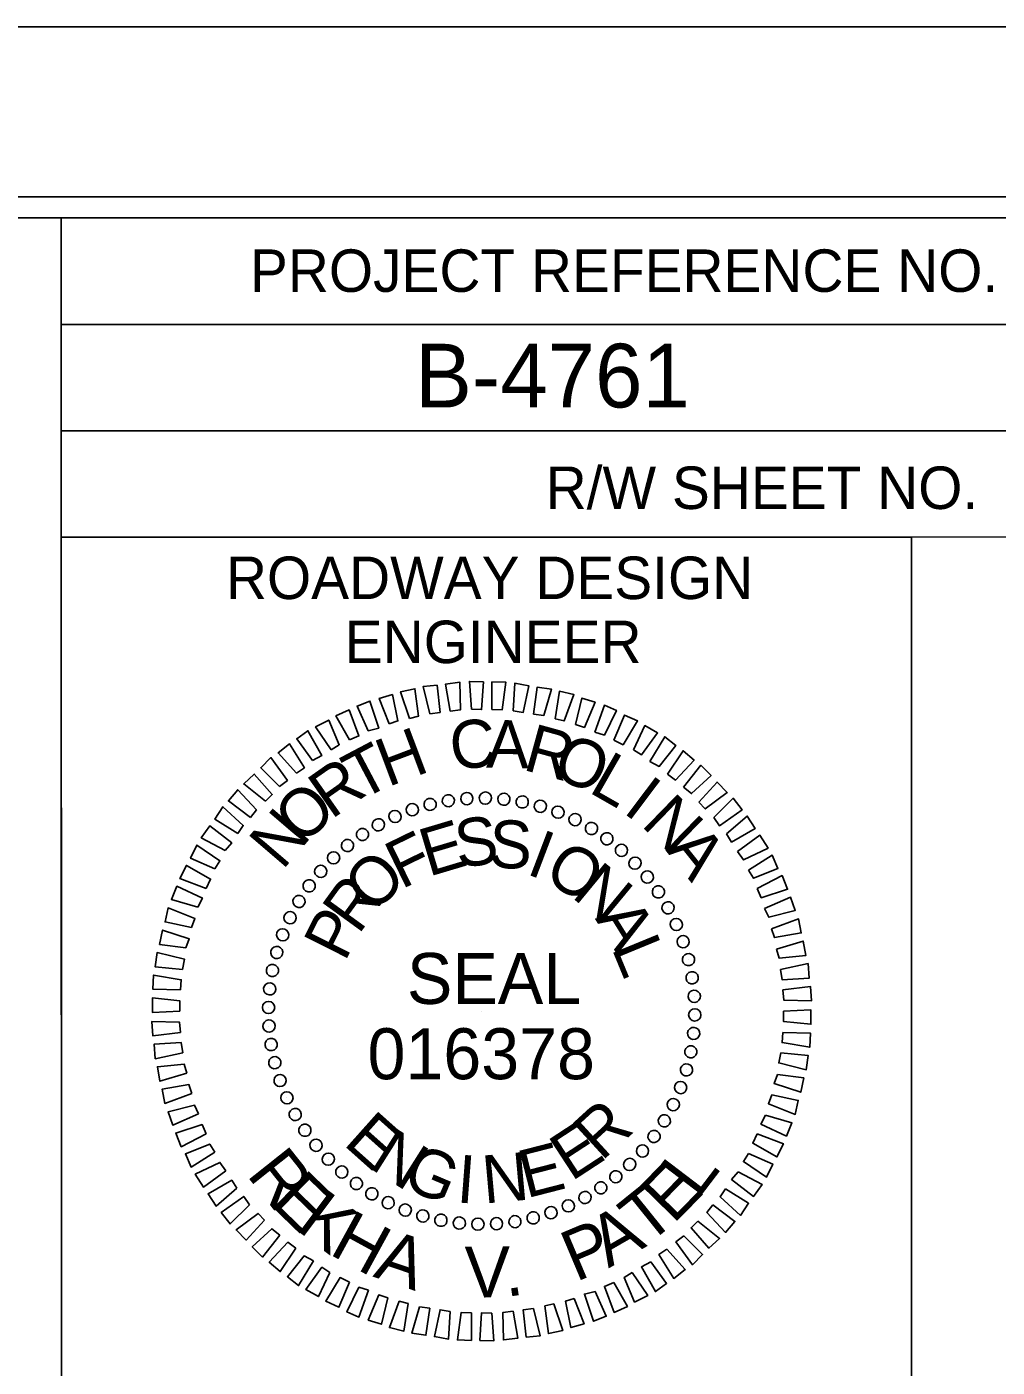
# Model space of a CAD drawing. Extents: x 1593595 to 1594166, y 741647 to 741854.
# Drawn here: x 1594114.83 to 1594128.53, y 741815.33 to 741834.26 of the extents above; entities that cross this region are included whole.
import ezdxf

# ---------------------------------------------------------------- set-up
doc = ezdxf.new("R2010")
doc.units = 0
for name, color, linetype in [('Sheet Cutting Line CELL', 7, 'Continuous'), ('Sheet Data Field CELL', 7, 'Continuous'), ('Sheet Plan CELL', 7, 'Continuous'), ('Sheet Plan Layout CELL', 7, 'Continuous'), ('Sheet Plot Border Inside CELL', 7, 'Continuous'), ('Sheet Plot Border Outside CELL', 7, 'Continuous'), ('Sheet Professional Seal CELL', 7, 'Continuous')]:
    doc.layers.add(name, color=color, linetype=linetype)

msp = doc.modelspace()

# ---------------------------------------------------------------- linework, layer by layer
at = {"layer": 'Sheet Cutting Line CELL'}
msp.add_line((1594141.358, 741834.259), (1593939.338, 741834.259), dxfattribs=at)
at = {"layer": 'Sheet Plan CELL'}
for p, q in [((1594115.31, 741830.056), (1594139.316, 741830.054)), ((1594115.312, 741828.551), (1594139.316, 741828.554)), ((1594115.312, 741828.551), (1594139.316, 741828.554)), ((1594115.312, 741828.551), (1594115.312, 741827.053)), ((1594127.318, 741827.053), (1594127.319, 741813.557))]:
    msp.add_line(p, q, dxfattribs=at)
for points in [[(1593959.316, 741705.56), (1593959.313, 741831.557), (1594115.312, 741831.562), (1594115.313, 741813.554), (1594139.318, 741813.553), (1594139.318, 741705.56)], [(1594139.321, 741831.56), (1593959.316, 741831.56), (1593959.316, 741705.56), (1594139.318, 741705.56)], [(1594115.312, 741831.562), (1594139.321, 741831.56), (1594139.316, 741828.554), (1594115.312, 741828.551)], [(1594115.312, 741827.053), (1594127.318, 741827.053), (1594127.318, 741813.551), (1594115.313, 741813.554)], [(1594127.318, 741827.053), (1594139.316, 741827.054), (1594139.318, 741813.553), (1594127.318, 741813.551)]]:
    msp.add_lwpolyline(points, close=True, dxfattribs=at)
at = {"layer": 'Sheet Plan Layout CELL'}
msp.add_lwpolyline([(1594110.606, 741806.182), (1594139.319, 741806.182), (1594139.322, 741831.56), (1594110.606, 741831.56)], close=True, dxfattribs=at)
at = {"layer": 'Sheet Plot Border Inside CELL'}
msp.add_lwpolyline([(1593940.898, 741705.259), (1594140.816, 741705.26), (1594140.818, 741831.859), (1593940.898, 741831.859)], close=True, dxfattribs=at)
at = {"layer": 'Sheet Plot Border Outside CELL'}
msp.add_lwpolyline([(1593939.338, 741702.859), (1594141.358, 741702.859), (1594141.358, 741834.259), (1593939.338, 741834.259)], close=True, dxfattribs=at)
at = {"layer": 'Sheet Professional Seal CELL'}
for p, q in [((1594120.516, 741823.279), (1594120.516, 741823.279)), ((1594120.78, 741823.327), (1594120.78, 741823.327)), ((1594121.038, 741823.363), (1594121.038, 741823.363)), ((1594121.302, 741823.369), (1594121.302, 741823.369)), ((1594121.566, 741823.351), (1594121.566, 741823.351)), ((1594121.824, 741823.309), (1594121.824, 741823.309)), ((1594122.076, 741823.255), (1594122.076, 741823.255)), ((1594120.024, 741823.111), (1594120.024, 741823.111)), ((1594120.264, 741823.207), (1594120.264, 741823.207)), ((1594122.328, 741823.171), (1594122.328, 741823.171)), ((1594122.568, 741823.063), (1594122.568, 741823.063)), ((1594119.562, 741822.853), (1594119.562, 741822.853)), ((1594119.79, 741822.991), (1594119.79, 741822.991)), ((1594122.802, 741822.943), (1594122.802, 741822.943)), ((1594119.352, 741822.703), (1594119.352, 741822.703)), ((1594123.018, 741822.793), (1594123.018, 741822.793)), ((1594119.154, 741822.523), (1594119.154, 741822.523)), ((1594123.228, 741822.631), (1594123.228, 741822.631)), ((1594118.974, 741822.337), (1594118.974, 741822.337)), ((1594123.414, 741822.451), (1594123.414, 741822.451)), ((1594118.812, 741822.127), (1594118.812, 741822.127)), ((1594123.594, 741822.253), (1594123.594, 741822.253)), ((1594118.662, 741821.911), (1594118.662, 741821.911)), ((1594123.744, 741822.043), (1594123.744, 741822.043)), ((1594123.882, 741821.815), (1594123.882, 741821.815)), ((1594118.542, 741821.677), (1594118.542, 741821.677)), ((1594124.002, 741821.581), (1594124.002, 741821.581)), ((1594118.434, 741821.437), (1594118.434, 741821.437)), ((1594124.098, 741821.341), (1594124.098, 741821.341)), ((1594118.35, 741821.185), (1594118.35, 741821.185)), ((1594124.17, 741821.089), (1594124.17, 741821.089)), ((1594118.296, 741820.933), (1594118.296, 741820.933)), ((1594124.218, 741820.825), (1594124.218, 741820.825)), ((1594118.254, 741820.675), (1594118.254, 741820.675)), ((1594118.236, 741820.411), (1594118.236, 741820.411)), ((1594124.254, 741820.567), (1594124.254, 741820.567)), ((1594121.248, 741820.357), (1594121.248, 741820.357)), ((1594124.26, 741820.303), (1594124.26, 741820.303)), ((1594118.242, 741820.147), (1594118.242, 741820.147)), ((1594124.242, 741820.039), (1594124.242, 741820.039)), ((1594118.278, 741819.889), (1594118.278, 741819.889)), ((1594124.2, 741819.781), (1594124.2, 741819.781)), ((1594118.326, 741819.625), (1594118.326, 741819.625)), ((1594124.146, 741819.529), (1594124.146, 741819.529)), ((1594118.398, 741819.373), (1594118.398, 741819.373)), ((1594124.062, 741819.277), (1594124.062, 741819.277)), ((1594118.494, 741819.133), (1594118.494, 741819.133)), ((1594118.614, 741818.899), (1594118.614, 741818.899)), ((1594123.954, 741819.037), (1594123.954, 741819.037)), ((1594123.834, 741818.803), (1594123.834, 741818.803)), ((1594118.752, 741818.671), (1594118.752, 741818.671)), ((1594123.684, 741818.587), (1594123.684, 741818.587)), ((1594118.902, 741818.461), (1594118.902, 741818.461)), ((1594123.522, 741818.377), (1594123.522, 741818.377)), ((1594119.082, 741818.263), (1594119.082, 741818.263)), ((1594123.342, 741818.191), (1594123.342, 741818.191)), ((1594119.268, 741818.083), (1594119.268, 741818.083)), ((1594123.144, 741818.011), (1594123.144, 741818.011)), ((1594119.478, 741817.921), (1594119.478, 741817.921)), ((1594119.694, 741817.771), (1594119.694, 741817.771)), ((1594122.934, 741817.861), (1594122.934, 741817.861)), ((1594119.928, 741817.651), (1594119.928, 741817.651)), ((1594122.472, 741817.603), (1594122.472, 741817.603)), ((1594122.706, 741817.723), (1594122.706, 741817.723)), ((1594120.168, 741817.543), (1594120.168, 741817.543)), ((1594120.42, 741817.459), (1594120.42, 741817.459)), ((1594120.672, 741817.405), (1594120.672, 741817.405)), ((1594120.93, 741817.363), (1594120.93, 741817.363)), ((1594121.716, 741817.387), (1594121.716, 741817.387)), ((1594121.98, 741817.435), (1594121.98, 741817.435)), ((1594122.232, 741817.507), (1594122.232, 741817.507)), ((1594121.194, 741817.345), (1594121.194, 741817.345)), ((1594121.458, 741817.351), (1594121.458, 741817.351))]:
    msp.add_line(p, q, dxfattribs=at)
for points in [[(1594120.516, 741824.557), (1594120.42, 741824.941), (1594120.618, 741824.959), (1594120.66, 741824.575)], [(1594120.804, 741824.593), (1594120.738, 741824.977), (1594120.942, 741825.001), (1594120.948, 741824.611)], [(1594121.104, 741824.623), (1594121.074, 741825.013), (1594121.272, 741825.007), (1594121.248, 741824.617)], [(1594121.392, 741824.617), (1594121.392, 741825.007), (1594121.59, 741825.001), (1594121.536, 741824.611)], [(1594121.692, 741824.599), (1594121.716, 741824.989), (1594121.914, 741824.953), (1594121.836, 741824.575)], [(1594121.98, 741824.551), (1594122.034, 741824.935), (1594122.232, 741824.905), (1594122.124, 741824.533)], [(1594119.94, 741824.413), (1594119.802, 741824.773), (1594119.988, 741824.827), (1594120.066, 741824.455)], [(1594120.228, 741824.491), (1594120.102, 741824.869), (1594120.306, 741824.911), (1594120.354, 741824.521)], [(1594122.286, 741824.485), (1594122.346, 741824.875), (1594122.55, 741824.827), (1594122.412, 741824.455)], [(1594122.574, 741824.407), (1594122.664, 741824.779), (1594122.85, 741824.719), (1594122.7, 741824.365)], [(1594119.382, 741824.191), (1594119.19, 741824.527), (1594119.376, 741824.611), (1594119.514, 741824.245)], [(1594119.646, 741824.317), (1594119.49, 741824.665), (1594119.67, 741824.737), (1594119.796, 741824.353)], [(1594122.844, 741824.299), (1594122.982, 741824.677), (1594123.15, 741824.605), (1594122.982, 741824.257)], [(1594119.124, 741824.047), (1594118.902, 741824.371), (1594119.088, 741824.467), (1594119.238, 741824.119)], [(1594123.114, 741824.185), (1594123.264, 741824.539), (1594123.45, 741824.455), (1594123.246, 741824.119)], [(1594123.39, 741824.047), (1594123.552, 741824.389), (1594123.732, 741824.287), (1594123.504, 741823.975)], [(1594118.86, 741823.897), (1594118.638, 741824.203), (1594118.794, 741824.317), (1594118.992, 741823.969)], [(1594123.624, 741823.885), (1594123.834, 741824.233), (1594123.99, 741824.107), (1594123.756, 741823.813)], [(1594118.632, 741823.717), (1594118.374, 741824.005), (1594118.536, 741824.131), (1594118.746, 741823.795)], [(1594123.87, 741823.705), (1594124.092, 741824.035), (1594124.248, 741823.903), (1594123.984, 741823.621)], [(1594118.392, 741823.531), (1594118.128, 741823.795), (1594118.272, 741823.939), (1594118.506, 741823.615)], [(1594124.098, 741823.519), (1594124.344, 741823.831), (1594124.488, 741823.687), (1594124.212, 741823.429)], [(1594118.194, 741823.321), (1594117.888, 741823.567), (1594118.038, 741823.705), (1594118.29, 741823.417)], [(1594117.984, 741823.093), (1594117.672, 741823.327), (1594117.804, 741823.483), (1594118.068, 741823.201)], [(1594124.314, 741823.309), (1594124.572, 741823.591), (1594124.716, 741823.447), (1594124.404, 741823.213)], [(1594117.804, 741822.865), (1594117.48, 741823.069), (1594117.594, 741823.243), (1594117.882, 741822.979)], [(1594124.524, 741823.093), (1594124.8, 741823.363), (1594124.926, 741823.201), (1594124.608, 741822.973)], [(1594124.704, 741822.859), (1594124.998, 741823.111), (1594125.112, 741822.937), (1594124.776, 741822.745)], [(1594117.624, 741822.625), (1594117.288, 741822.805), (1594117.408, 741822.973), (1594117.72, 741822.733)], [(1594117.48, 741822.367), (1594117.138, 741822.517), (1594117.228, 741822.703), (1594117.552, 741822.481)], [(1594124.86, 741822.613), (1594125.178, 741822.841), (1594125.292, 741822.661), (1594124.944, 741822.493)], [(1594125.016, 741822.349), (1594125.352, 741822.559), (1594125.43, 741822.373), (1594125.088, 741822.235)], [(1594117.36, 741822.091), (1594116.988, 741822.229), (1594117.078, 741822.415), (1594117.42, 741822.223)], [(1594117.24, 741821.827), (1594116.868, 741821.935), (1594116.946, 741822.121), (1594117.306, 741821.953)], [(1594125.136, 741822.091), (1594125.49, 741822.271), (1594125.568, 741822.079), (1594125.196, 741821.959)], [(1594125.244, 741821.809), (1594125.61, 741821.965), (1594125.676, 741821.779), (1594125.304, 741821.683)], [(1594117.15, 741821.539), (1594116.778, 741821.617), (1594116.82, 741821.815), (1594117.198, 741821.665)], [(1594125.34, 741821.521), (1594125.724, 741821.659), (1594125.76, 741821.461), (1594125.382, 741821.395)], [(1594117.072, 741821.251), (1594116.7, 741821.299), (1594116.742, 741821.503), (1594117.12, 741821.377)], [(1594125.412, 741821.233), (1594125.79, 741821.347), (1594125.826, 741821.143), (1594125.448, 741821.107)], [(1594117.024, 741820.945), (1594116.64, 741820.981), (1594116.664, 741821.185), (1594117.054, 741821.089)], [(1594125.466, 741820.945), (1594125.856, 741821.029), (1594125.874, 741820.825), (1594125.49, 741820.801)], [(1594116.994, 741820.657), (1594116.604, 741820.669), (1594116.616, 741820.867), (1594117.006, 741820.801)], [(1594125.502, 741820.657), (1594125.892, 741820.705), (1594125.904, 741820.501), (1594125.514, 741820.513)], [(1594116.988, 741820.357), (1594116.598, 741820.339), (1594116.598, 741820.543), (1594116.988, 741820.501)], [(1594116.994, 741820.057), (1594116.604, 741820.009), (1594116.592, 741820.213), (1594116.982, 741820.201)], [(1594125.508, 741820.357), (1594125.898, 741820.375), (1594125.898, 741820.171), (1594125.508, 741820.213)], [(1594125.502, 741820.057), (1594125.892, 741820.045), (1594125.88, 741819.847), (1594125.49, 741819.913)], [(1594117.03, 741819.769), (1594116.64, 741819.685), (1594116.622, 741819.889), (1594117.006, 741819.913)], [(1594125.472, 741819.769), (1594125.856, 741819.733), (1594125.832, 741819.529), (1594125.442, 741819.625)], [(1594117.084, 741819.481), (1594116.706, 741819.367), (1594116.67, 741819.571), (1594117.048, 741819.607)], [(1594125.424, 741819.463), (1594125.796, 741819.415), (1594125.754, 741819.211), (1594125.376, 741819.337)], [(1594117.156, 741819.193), (1594116.772, 741819.055), (1594116.736, 741819.253), (1594117.114, 741819.319)], [(1594125.346, 741819.175), (1594125.718, 741819.097), (1594125.676, 741818.899), (1594125.298, 741819.049)], [(1594117.252, 741818.905), (1594116.886, 741818.749), (1594116.82, 741818.935), (1594117.192, 741819.031)], [(1594125.256, 741818.887), (1594125.628, 741818.779), (1594125.55, 741818.593), (1594125.19, 741818.761)], [(1594117.36, 741818.623), (1594117.006, 741818.443), (1594116.928, 741818.635), (1594117.3, 741818.755)], [(1594125.136, 741818.623), (1594125.508, 741818.485), (1594125.418, 741818.299), (1594125.076, 741818.491)], [(1594117.48, 741818.365), (1594117.144, 741818.155), (1594117.066, 741818.341), (1594117.408, 741818.479)], [(1594125.016, 741818.347), (1594125.358, 741818.197), (1594125.268, 741818.011), (1594124.944, 741818.233)], [(1594117.636, 741818.101), (1594117.318, 741817.873), (1594117.204, 741818.053), (1594117.552, 741818.221)], [(1594117.792, 741817.855), (1594117.498, 741817.603), (1594117.384, 741817.777), (1594117.72, 741817.969)], [(1594124.872, 741818.089), (1594125.208, 741817.909), (1594125.088, 741817.741), (1594124.776, 741817.981)], [(1594117.972, 741817.621), (1594117.696, 741817.351), (1594117.57, 741817.513), (1594117.888, 741817.741)], [(1594124.692, 741817.849), (1594125.016, 741817.645), (1594124.902, 741817.471), (1594124.614, 741817.735)], [(1594124.512, 741817.621), (1594124.824, 741817.387), (1594124.692, 741817.231), (1594124.428, 741817.513)], [(1594118.182, 741817.405), (1594117.924, 741817.123), (1594117.78, 741817.267), (1594118.092, 741817.501)], [(1594124.302, 741817.393), (1594124.608, 741817.147), (1594124.458, 741817.009), (1594124.206, 741817.297)], [(1594118.398, 741817.195), (1594118.152, 741816.883), (1594118.008, 741817.027), (1594118.284, 741817.285)], [(1594124.104, 741817.183), (1594124.368, 741816.919), (1594124.224, 741816.775), (1594123.99, 741817.099)], [(1594118.626, 741817.009), (1594118.404, 741816.679), (1594118.248, 741816.811), (1594118.512, 741817.093)], [(1594123.864, 741816.997), (1594124.122, 741816.709), (1594123.96, 741816.583), (1594123.75, 741816.919)], [(1594118.872, 741816.829), (1594118.662, 741816.481), (1594118.506, 741816.607), (1594118.74, 741816.901)], [(1594123.636, 741816.817), (1594123.858, 741816.511), (1594123.702, 741816.397), (1594123.504, 741816.745)], [(1594119.106, 741816.667), (1594118.944, 741816.325), (1594118.764, 741816.427), (1594118.992, 741816.739)], [(1594123.372, 741816.667), (1594123.594, 741816.343), (1594123.408, 741816.247), (1594123.258, 741816.595)], [(1594119.382, 741816.529), (1594119.232, 741816.175), (1594119.046, 741816.259), (1594119.25, 741816.595)], [(1594119.652, 741816.415), (1594119.514, 741816.037), (1594119.346, 741816.109), (1594119.514, 741816.457)], [(1594123.114, 741816.523), (1594123.306, 741816.187), (1594123.12, 741816.103), (1594122.982, 741816.469)], [(1594119.922, 741816.307), (1594119.832, 741815.935), (1594119.646, 741815.995), (1594119.796, 741816.349)], [(1594120.21, 741816.229), (1594120.15, 741815.839), (1594119.946, 741815.887), (1594120.084, 741816.259)], [(1594122.268, 741816.223), (1594122.394, 741815.845), (1594122.19, 741815.803), (1594122.142, 741816.193)], [(1594122.556, 741816.301), (1594122.694, 741815.941), (1594122.508, 741815.887), (1594122.43, 741816.259)], [(1594122.85, 741816.397), (1594123.006, 741816.049), (1594122.826, 741815.977), (1594122.7, 741816.361)], [(1594120.516, 741816.163), (1594120.462, 741815.779), (1594120.264, 741815.809), (1594120.372, 741816.181)], [(1594120.804, 741816.115), (1594120.78, 741815.725), (1594120.582, 741815.761), (1594120.66, 741816.139)], [(1594121.104, 741816.097), (1594121.104, 741815.707), (1594120.906, 741815.713), (1594120.96, 741816.103)], [(1594121.392, 741816.091), (1594121.422, 741815.701), (1594121.224, 741815.707), (1594121.248, 741816.097)], [(1594121.692, 741816.121), (1594121.758, 741815.737), (1594121.554, 741815.713), (1594121.548, 741816.103)], [(1594121.98, 741816.157), (1594122.076, 741815.773), (1594121.878, 741815.755), (1594121.836, 741816.139)]]:
    msp.add_lwpolyline(points, close=True, dxfattribs=at)
for centre, major_axis in [((1594120.777, 741823.329), (-0.0135, 0.0853)), ((1594121.038, 741823.359), (-0.006, 0.0862)), ((1594121.3, 741823.366), (0.0015, 0.0864)), ((1594121.562, 741823.35), (0.009, 0.0859)), ((1594120.268, 741823.202), (-0.0281, 0.0817)), ((1594120.52, 741823.277), (-0.0209, 0.0838)), ((1594121.822, 741823.311), (0.0165, 0.0848)), ((1594122.077, 741823.25), (0.0238, 0.0831)), ((1594122.326, 741823.167), (0.031, 0.0807)), ((1594119.789, 741822.989), (-0.0419, 0.0756)), ((1594120.024, 741823.106), (-0.0351, 0.0789)), ((1594122.567, 741823.062), (0.0379, 0.0777)), ((1594119.565, 741822.852), (-0.0483, 0.0716)), ((1594122.798, 741822.937), (0.0445, 0.0741)), ((1594123.017, 741822.792), (0.0508, 0.0699)), ((1594119.354, 741822.696), (-0.0544, 0.0671)), ((1594123.222, 741822.628), (0.0567, 0.0652)), ((1594119.157, 741822.522), (-0.06, 0.0622)), ((1594123.413, 741822.447), (0.0622, 0.06)), ((1594118.976, 741822.331), (-0.0652, 0.0567)), ((1594123.587, 741822.251), (0.0671, 0.0544)), ((1594118.813, 741822.126), (-0.0699, 0.0508)), ((1594123.743, 741822.04), (0.0716, 0.0483)), ((1594118.668, 741821.907), (-0.0741, 0.0445)), ((1594123.88, 741821.816), (0.0756, 0.0419)), ((1594118.543, 741821.676), (-0.0777, 0.0379)), ((1594118.438, 741821.435), (-0.0807, 0.031)), ((1594123.997, 741821.581), (0.0789, 0.0351)), ((1594124.093, 741821.337), (0.0817, 0.0281)), ((1594118.355, 741821.186), (-0.0831, 0.0238)), ((1594124.168, 741821.085), (0.0838, 0.0209)), ((1594118.293, 741820.931), (-0.0848, 0.0165)), ((1594124.22, 741820.828), (0.0853, 0.0135)), ((1594118.255, 741820.671), (-0.0859, 0.009)), ((1594124.25, 741820.567), (0.0862, 0.006)), ((1594118.239, 741820.409), (-0.0864, 0.0015)), ((1594124.257, 741820.304), (0.0864, -0.0015)), ((1594118.245, 741820.147), (-0.0862, -0.006)), ((1594124.241, 741820.042), (0.0859, -0.009)), ((1594118.275, 741819.886), (-0.0853, -0.0135)), ((1594124.202, 741819.783), (0.0848, -0.0165)), ((1594118.327, 741819.629), (-0.0838, -0.0209)), ((1594118.402, 741819.377), (-0.0817, -0.0281)), ((1594124.141, 741819.527), (0.0831, -0.0238)), ((1594124.057, 741819.278), (0.0807, -0.031)), ((1594118.498, 741819.133), (-0.0789, -0.0351)), ((1594123.953, 741819.037), (0.0777, -0.0379)), ((1594118.615, 741818.898), (-0.0756, -0.0419)), ((1594123.827, 741818.807), (0.0741, -0.0445)), ((1594118.753, 741818.674), (-0.0716, -0.0483)), ((1594123.682, 741818.588), (0.0699, -0.0508)), ((1594118.909, 741818.463), (-0.0671, -0.0544)), ((1594119.083, 741818.266), (-0.0622, -0.06)), ((1594123.519, 741818.382), (0.0652, -0.0567)), ((1594119.273, 741818.085), (-0.0567, -0.0652)), ((1594123.142, 741818.018), (0.0544, -0.0671)), ((1594123.338, 741818.192), (0.06, -0.0622)), ((1594119.479, 741817.922), (-0.0508, -0.0699)), ((1594122.931, 741817.862), (0.0483, -0.0716)), ((1594119.698, 741817.777), (-0.0445, -0.0741)), ((1594119.928, 741817.652), (-0.0379, -0.0777)), ((1594122.707, 741817.725), (0.0419, -0.0756)), ((1594120.169, 741817.547), (-0.031, -0.0807)), ((1594120.418, 741817.464), (-0.0238, -0.0831)), ((1594122.227, 741817.511), (0.0281, -0.0817)), ((1594122.472, 741817.607), (0.0351, -0.0789)), ((1594120.673, 741817.403), (-0.0165, -0.0848)), ((1594120.933, 741817.364), (-0.009, -0.0859)), ((1594121.195, 741817.348), (-0.0015, -0.0864)), ((1594121.458, 741817.355), (0.006, -0.0862)), ((1594121.718, 741817.384), (0.0135, -0.0853)), ((1594121.976, 741817.437), (0.0209, -0.0838))]:
    msp.add_ellipse(centre, major_axis=major_axis, ratio=0.999708, dxfattribs=at)

# ---------------------------------------------------------------- texts
at = {"layer": 'Sheet Data Field CELL'}
msp.add_text(' B-4761  ', height=0.9, rotation=0, dxfattribs=at).set_placement((1594119.973, 741828.883))
at = {"layer": 'Sheet Plan CELL'}
for s, height, p in [('PROJECT REFERENCE NO.', 0.60001, (1594117.976, 741830.515)), ('R/W SHEET NO.', 0.60001, (1594122.152, 741827.449)), ('ROADWAY DESIGN', 0.60001, (1594117.637, 741826.177)), ('ENGINEER', 0.6, (1594119.315, 741825.272))]:
    msp.add_text(s, height=height, rotation=0, dxfattribs=at).set_placement(p)
at = {"layer": 'Sheet Professional Seal CELL'}
for s, height, rotation, p in [('C', 0.677, 6.2199, (1594120.834, 741823.759)), ('A', 0.677, 359.0203, (1594121.308, 741823.795)), ('R', 0.677, 344.6211, (1594121.812, 741823.771)), ('H', 0.677, 20.6195, (1594119.922, 741823.519)), ('O', 0.677, 337.4212, (1594122.214, 741823.681)), ('T', 0.677, 27.8198, (1594119.532, 741823.321)), ('L', 0.677, 330.2209, (1594122.742, 741823.459)), ('R', 0.677, 35.0205, (1594119.124, 741823.057)), ('I', 0.677, 323.0201, (1594123.228, 741823.171)), ('O', 0.677, 42.2217, (1594118.71, 741822.685)), ('N', 0.677, 315.8189, (1594123.486, 741822.985)), ('N', 0.677, 49.4235, (1594118.434, 741822.337)), ('E', 0.677, 16.6111, (1594120.498, 741822.253)), ('S', 0.677, 7.2556, (1594120.912, 741822.379)), ('S', 0.677, 357.9004, (1594121.344, 741822.385)), ('F', 0.677, 25.967, (1594120.114, 741822.073)), ('I', 0.677, 339.1896, (1594121.86, 741822.301)), ('A', 0.677, 308.6172, (1594123.84, 741822.631)), ('O', 0.677, 329.8335, (1594122.1, 741822.217)), ('O', 0.677, 44.6812, (1594119.718, 741821.719)), ('N', 0.677, 320.4766, (1594122.502, 741821.977)), ('R', 0.677, 54.0397, (1594119.508, 741821.425)), ('P', 0.677, 63.3989, (1594119.316, 741821.041)), ('A', 0.677, 301.7603, (1594122.844, 741821.665)), ('L', 0.677, 292.4008, (1594123.078, 741821.251)), ('SEAL', 0.7198, 360, (1594120.192, 741820.459)), ('E', 0.677, 318.2769, (1594119.28, 741818.479)), ('R', 0.677, 42.4814, (1594122.94, 741818.227)), ('N', 0.677, 327.634, (1594119.64, 741818.155)), ('E', 0.677, 33.1241, (1594122.514, 741817.945)), ('E', 0.677, 14.4118, (1594121.878, 741817.711)), ('R', 0.72, 308.4805, (1594117.918, 741818.047)), ('G', 0.677, 336.9902, (1594120.096, 741817.885)), ('I', 0.677, 355.7012, (1594120.882, 741817.657)), ('N', 0.677, 5.0564, (1594121.284, 741817.639)), ('E', 0.72, 45.6157, (1594123.953, 741817.339)), ('L', 0.72, 52.725, (1594124.306, 741817.697)), ('E', 0.72, 315.9607, (1594118.247, 741817.633)), ('T', 0.72, 38.8154, (1594123.577, 741817.04)), ('K', 0.72, 323.0701, (1594118.607, 741817.283)), ('H', 0.72, 331.354, (1594119.077, 741816.934)), ('P', 0.72, 22.8658, (1594122.576, 741816.528)), ('A', 0.72, 29.9751, (1594123.039, 741816.722)), ('A', 0.72, 341.338, (1594119.703, 741816.61)), ('V', 0.72, 0.3786, (1594121.01, 741816.311)), ('.', 0.72, 8.6317, (1594121.594, 741816.319))]:
    msp.add_text(s, height=height, rotation=rotation, dxfattribs=at).set_placement(p)
msp.add_text('016378', height=0.7198, dxfattribs=at).set_placement((1594119.636, 741819.396))

doc.saveas('drawing.dxf')
